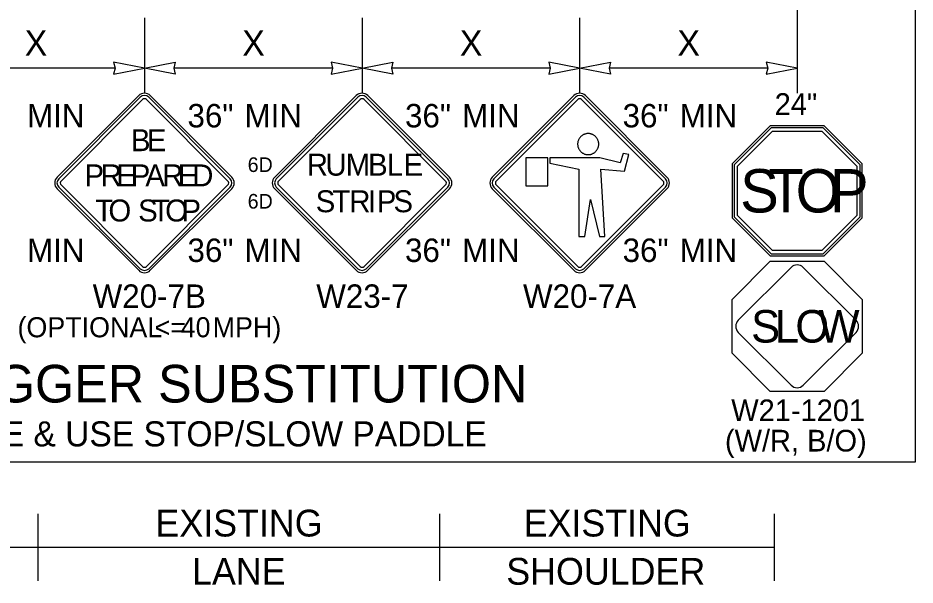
# Model space of a CAD drawing. Extents: x 99999.1 to 100095.7, y 99995 to 100010.7.
# Drawn here: x 100006.43 to 100009.11, y 100003.112 to 100004.807 of the extents above; entities that cross this region are included whole.
import ezdxf

# ---------------------------------------------------------------- set-up
doc = ezdxf.new("R2010")
doc.units = 0
for name, color, linetype in [('SH_DE_DetailHeading2Text', 7, 'Continuous'), ('TR_SN_ConstructionSigns', 7, 'Continuous'), ('TR_WZ_WorkZoneDetails', 7, 'Continuous'), ('TR_WZ_WorkZoneTextCurrent', 7, 'Continuous')]:
    doc.layers.add(name, color=color, linetype=linetype)

msp = doc.modelspace()

# ---------------------------------------------------------------- linework, layer by layer
at = {"layer": 'TR_SN_ConstructionSigns'}
for p, q in [((100006.7907, 100004.5751), (100006.5471, 100004.3315)), ((100007.0691, 100004.3315), (100006.8255, 100004.5751)), ((100007.4407, 100004.5751), (100007.1971, 100004.3315)), ((100007.7191, 100004.3315), (100007.4755, 100004.5751)), ((100008.0907, 100004.5751), (100007.8471, 100004.3315)), ((100008.3691, 100004.3315), (100008.1255, 100004.5751)), ((100006.7955, 100004.5703), (100006.5519, 100004.3267)), ((100006.5587, 100004.3199), (100006.8023, 100004.5635)), ((100006.8139, 100004.5635), (100007.0575, 100004.3199)), ((100007.0643, 100004.3267), (100006.8207, 100004.5703)), ((100007.4455, 100004.5703), (100007.2019, 100004.3267)), ((100007.2087, 100004.3199), (100007.4523, 100004.5635)), ((100007.4639, 100004.5635), (100007.7075, 100004.3199)), ((100007.7143, 100004.3267), (100007.4707, 100004.5703)), ((100008.0955, 100004.5703), (100007.8519, 100004.3267)), ((100007.8587, 100004.3199), (100008.1023, 100004.5635)), ((100008.1139, 100004.5635), (100008.3575, 100004.3199)), ((100008.3643, 100004.3267), (100008.1207, 100004.5703)), ((100008.6775, 100004.4851), (100008.5636, 100004.3713)), ((100008.68, 100004.4791), (100008.5697, 100004.3687)), ((100008.5798, 100004.3646), (100008.6842, 100004.4689)), ((100008.8385, 100004.4851), (100008.6775, 100004.4851)), ((100008.836, 100004.4791), (100008.68, 100004.4791)), ((100008.6842, 100004.4689), (100008.8318, 100004.4689)), ((100008.8318, 100004.4689), (100008.9362, 100004.3646)), ((100008.9463, 100004.3687), (100008.836, 100004.4791)), ((100008.9524, 100004.3713), (100008.8385, 100004.4851)), ((100008.1043, 100004.4417), (100008.1037, 100004.4401)), ((100008.1049, 100004.4433), (100008.1043, 100004.4417)), ((100008.1056, 100004.4448), (100008.1049, 100004.4433)), ((100008.1064, 100004.4463), (100008.1056, 100004.4448)), ((100008.1074, 100004.4477), (100008.1064, 100004.4463)), ((100008.1083, 100004.4491), (100008.1074, 100004.4477)), ((100008.1093, 100004.4504), (100008.1083, 100004.4491)), ((100008.1104, 100004.4516), (100008.1093, 100004.4504)), ((100008.1116, 100004.4528), (100008.1104, 100004.4516)), ((100008.1128, 100004.454), (100008.1116, 100004.4528)), ((100008.1142, 100004.455), (100008.1128, 100004.454)), ((100008.1155, 100004.456), (100008.1142, 100004.455)), ((100008.1169, 100004.4569), (100008.1155, 100004.456)), ((100008.1183, 100004.4578), (100008.1169, 100004.4569)), ((100008.1199, 100004.4586), (100008.1183, 100004.4578)), ((100008.1213, 100004.4593), (100008.1199, 100004.4586)), ((100008.1229, 100004.4599), (100008.1213, 100004.4593)), ((100008.1245, 100004.4604), (100008.1229, 100004.4599)), ((100008.1262, 100004.4608), (100008.1245, 100004.4604)), ((100008.1278, 100004.4612), (100008.1262, 100004.4608)), ((100008.1294, 100004.4615), (100008.1278, 100004.4612)), ((100008.1311, 100004.4616), (100008.1294, 100004.4615)), ((100008.1328, 100004.4618), (100008.1311, 100004.4616)), ((100008.1345, 100004.4618), (100008.1328, 100004.4618)), ((100008.1361, 100004.4616), (100008.1345, 100004.4618)), ((100008.1378, 100004.4615), (100008.1361, 100004.4616)), ((100008.1395, 100004.4612), (100008.1378, 100004.4615)), ((100008.1411, 100004.4608), (100008.1395, 100004.4612)), ((100008.1427, 100004.4604), (100008.1411, 100004.4608)), ((100008.1443, 100004.4599), (100008.1427, 100004.4604)), ((100008.1459, 100004.4593), (100008.1443, 100004.4599)), ((100008.1474, 100004.4586), (100008.1459, 100004.4593)), ((100008.1489, 100004.4578), (100008.1474, 100004.4586)), ((100008.1503, 100004.4569), (100008.1489, 100004.4578)), ((100008.1517, 100004.456), (100008.1503, 100004.4569)), ((100008.1531, 100004.455), (100008.1517, 100004.456)), ((100008.1543, 100004.454), (100008.1531, 100004.455)), ((100008.1556, 100004.4528), (100008.1543, 100004.454)), ((100008.1568, 100004.4516), (100008.1556, 100004.4528)), ((100008.1579, 100004.4504), (100008.1568, 100004.4516)), ((100008.1589, 100004.4491), (100008.1579, 100004.4504)), ((100008.1599, 100004.4477), (100008.1589, 100004.4491)), ((100008.1608, 100004.4463), (100008.1599, 100004.4477)), ((100008.1616, 100004.4448), (100008.1608, 100004.4463)), ((100008.1623, 100004.4433), (100008.1616, 100004.4448)), ((100008.1629, 100004.4417), (100008.1623, 100004.4433)), ((100008.1635, 100004.4401), (100008.1629, 100004.4417)), ((100008.1023, 100004.4336), (100008.1021, 100004.4319)), ((100008.1021, 100004.4319), (100008.1021, 100004.4302)), ((100008.1021, 100004.4302), (100008.1021, 100004.4286)), ((100008.1021, 100004.4286), (100008.1023, 100004.4269)), ((100008.1025, 100004.4353), (100008.1023, 100004.4336)), ((100008.1023, 100004.4269), (100008.1025, 100004.4252)), ((100008.1028, 100004.4369), (100008.1025, 100004.4353)), ((100008.1025, 100004.4252), (100008.1028, 100004.4236)), ((100008.1032, 100004.4385), (100008.1028, 100004.4369)), ((100008.1028, 100004.4236), (100008.1032, 100004.422)), ((100008.1037, 100004.4401), (100008.1032, 100004.4385)), ((100008.1032, 100004.422), (100008.1037, 100004.4204)), ((100008.1037, 100004.4204), (100008.1043, 100004.4188)), ((100008.1043, 100004.4188), (100008.1049, 100004.4172)), ((100008.1049, 100004.4172), (100008.1056, 100004.4157)), ((100008.1056, 100004.4157), (100008.1064, 100004.4142)), ((100008.1064, 100004.4142), (100008.1074, 100004.4128)), ((100008.1599, 100004.4128), (100008.1608, 100004.4142)), ((100008.1608, 100004.4142), (100008.1616, 100004.4157)), ((100008.1616, 100004.4157), (100008.1623, 100004.4172)), ((100008.1623, 100004.4172), (100008.1629, 100004.4188)), ((100008.1629, 100004.4188), (100008.1635, 100004.4204)), ((100008.164, 100004.4385), (100008.1635, 100004.4401)), ((100008.1635, 100004.4204), (100008.164, 100004.422)), ((100008.1644, 100004.4369), (100008.164, 100004.4385)), ((100008.164, 100004.422), (100008.1644, 100004.4236)), ((100008.1647, 100004.4353), (100008.1644, 100004.4369)), ((100008.1644, 100004.4236), (100008.1647, 100004.4252)), ((100008.165, 100004.4336), (100008.1647, 100004.4353)), ((100008.1647, 100004.4252), (100008.165, 100004.4269)), ((100008.1651, 100004.4319), (100008.165, 100004.4336)), ((100008.165, 100004.4269), (100008.1651, 100004.4286)), ((100008.1651, 100004.4302), (100008.1651, 100004.4319)), ((100008.1651, 100004.4286), (100008.1651, 100004.4302)), ((100007.9469, 100004.3888), (100007.9469, 100004.306)), ((100008.0128, 100004.3888), (100007.9469, 100004.3888)), ((100008.0128, 100004.306), (100008.0128, 100004.3888)), ((100008.1689, 100004.3888), (100008.0189, 100004.3888)), ((100008.0189, 100004.3888), (100008.0189, 100004.373)), ((100008.1074, 100004.4128), (100008.1083, 100004.4114)), ((100008.1083, 100004.4114), (100008.1093, 100004.4101)), ((100008.1093, 100004.4101), (100008.1104, 100004.4089)), ((100008.1104, 100004.4089), (100008.1116, 100004.4077)), ((100008.1116, 100004.4077), (100008.1128, 100004.4065)), ((100008.1128, 100004.4065), (100008.1142, 100004.4055)), ((100008.1142, 100004.4055), (100008.1155, 100004.4044)), ((100008.1155, 100004.4044), (100008.1169, 100004.4035)), ((100008.1169, 100004.4035), (100008.1183, 100004.4027)), ((100008.1183, 100004.4027), (100008.1199, 100004.4019)), ((100008.1199, 100004.4019), (100008.1213, 100004.4012)), ((100008.1213, 100004.4012), (100008.1229, 100004.4006)), ((100008.1229, 100004.4006), (100008.1245, 100004.4001)), ((100008.1245, 100004.4001), (100008.1262, 100004.3996)), ((100008.1262, 100004.3996), (100008.1278, 100004.3993)), ((100008.1278, 100004.3993), (100008.1294, 100004.399)), ((100008.1294, 100004.399), (100008.1311, 100004.3988)), ((100008.1311, 100004.3988), (100008.1328, 100004.3987)), ((100008.1328, 100004.3987), (100008.1345, 100004.3987)), ((100008.1345, 100004.3987), (100008.1361, 100004.3988)), ((100008.1361, 100004.3988), (100008.1378, 100004.399)), ((100008.1378, 100004.399), (100008.1395, 100004.3993)), ((100008.1395, 100004.3993), (100008.1411, 100004.3996)), ((100008.1411, 100004.3996), (100008.1427, 100004.4001)), ((100008.1427, 100004.4001), (100008.1443, 100004.4006)), ((100008.1443, 100004.4006), (100008.1459, 100004.4012)), ((100008.1459, 100004.4012), (100008.1474, 100004.4019)), ((100008.1474, 100004.4019), (100008.1489, 100004.4027)), ((100008.1489, 100004.4027), (100008.1503, 100004.4035)), ((100008.1503, 100004.4035), (100008.1517, 100004.4044)), ((100008.1517, 100004.4044), (100008.1531, 100004.4055)), ((100008.1531, 100004.4055), (100008.1543, 100004.4065)), ((100008.1543, 100004.4065), (100008.1556, 100004.4077)), ((100008.1556, 100004.4077), (100008.1568, 100004.4089)), ((100008.1568, 100004.4089), (100008.1579, 100004.4101)), ((100008.1579, 100004.4101), (100008.1589, 100004.4114)), ((100008.1589, 100004.4114), (100008.1599, 100004.4128)), ((100008.2297, 100004.3738), (100008.1689, 100004.3888)), ((100008.2382, 100004.4026), (100008.2297, 100004.3738)), ((100008.2556, 100004.3995), (100008.2382, 100004.4026)), ((100008.2425, 100004.3497), (100008.2556, 100004.3995)), ((100008.0189, 100004.373), (100008.106, 100004.3557)), ((100008.5636, 100004.3713), (100008.5636, 100004.2102)), ((100008.5697, 100004.3687), (100008.5697, 100004.2127)), ((100008.5798, 100004.2169), (100008.5798, 100004.3646)), ((100008.9362, 100004.3646), (100008.9362, 100004.2169)), ((100008.9463, 100004.2127), (100008.9463, 100004.3687)), ((100008.9524, 100004.2102), (100008.9524, 100004.3713)), ((100008.106, 100004.3557), (100008.106, 100004.1541)), ((100008.1831, 100004.1541), (100008.1717, 100004.3558)), ((100008.1717, 100004.3558), (100008.2425, 100004.3497)), ((100006.8023, 100004.0647), (100006.5587, 100004.3083)), ((100007.0575, 100004.3083), (100006.8139, 100004.0647)), ((100007.4523, 100004.0647), (100007.2087, 100004.3083)), ((100007.7075, 100004.3083), (100007.4639, 100004.0647)), ((100008.1023, 100004.0647), (100007.8587, 100004.3083)), ((100008.3575, 100004.3083), (100008.1139, 100004.0647)), ((100006.5471, 100004.2967), (100006.7907, 100004.0531)), ((100006.5519, 100004.3015), (100006.7955, 100004.0579)), ((100006.8207, 100004.0579), (100007.0643, 100004.3015)), ((100006.8255, 100004.0531), (100007.0691, 100004.2967)), ((100007.1971, 100004.2967), (100007.4407, 100004.0531)), ((100007.2019, 100004.3015), (100007.4455, 100004.0579)), ((100007.4707, 100004.0579), (100007.7143, 100004.3015)), ((100007.4755, 100004.0531), (100007.7191, 100004.2967)), ((100007.8471, 100004.2967), (100008.0907, 100004.0531)), ((100007.8519, 100004.3015), (100008.0955, 100004.0579)), ((100007.9469, 100004.306), (100008.0128, 100004.306)), ((100008.1207, 100004.0579), (100008.3643, 100004.3015)), ((100008.1255, 100004.0531), (100008.3691, 100004.2967)), ((100008.1236, 100004.1541), (100008.1408, 100004.265)), ((100008.1408, 100004.265), (100008.1673, 100004.1541)), ((100008.5636, 100004.2102), (100008.6775, 100004.0963)), ((100008.5697, 100004.2127), (100008.68, 100004.1024)), ((100008.6842, 100004.1125), (100008.5798, 100004.2169)), ((100008.9362, 100004.2169), (100008.8318, 100004.1125)), ((100008.836, 100004.1024), (100008.9463, 100004.2127)), ((100008.8385, 100004.0963), (100008.9524, 100004.2102)), ((100008.106, 100004.1541), (100008.1236, 100004.1541)), ((100008.1673, 100004.1541), (100008.1831, 100004.1541)), ((100008.6775, 100004.0963), (100008.8385, 100004.0963)), ((100008.68, 100004.1024), (100008.836, 100004.1024)), ((100008.8318, 100004.1125), (100008.6842, 100004.1125)), ((100008.7397, 100004.0618), (100008.5819, 100003.9041)), ((100008.9341, 100003.9041), (100008.7763, 100004.0618)), ((100008.5819, 100003.8674), (100008.7397, 100003.7097)), ((100008.7763, 100003.7097), (100008.9341, 100003.8674))]:
    msp.add_line(p, q, dxfattribs=at)
msp.add_lwpolyline([(100008.9524, 100003.9663), (100008.9524, 100003.8052), (100008.8385, 100003.6913), (100008.6775, 100003.6913), (100008.5636, 100003.8052), (100008.5636, 100003.9663), (100008.6775, 100004.0801), (100008.8385, 100004.0801)], close=True, dxfattribs=at)
for centre, radius, start, end in [((100006.8081, 100004.5577), 0.0246, 45, 135), ((100006.8081, 100004.5577), 0.0178, 45, 135), ((100007.4581, 100004.5577), 0.0246, 45, 135), ((100007.4581, 100004.5577), 0.0178, 45, 135), ((100008.1081, 100004.5577), 0.0246, 45, 135), ((100008.1081, 100004.5577), 0.0178, 45, 135), ((100006.8081, 100004.5577), 0.0082, 45, 135), ((100007.4581, 100004.5577), 0.0082, 45, 135), ((100008.1081, 100004.5577), 0.0082, 45, 135), ((100006.5645, 100004.3141), 0.0246, 135, 225), ((100006.5645, 100004.3141), 0.0178, 135, 225), ((100006.5645, 100004.3141), 0.0082, 135, 225), ((100007.0517, 100004.3141), 0.0082, 315, 45), ((100007.0517, 100004.3141), 0.0178, 315, 45), ((100007.0517, 100004.3141), 0.0246, 315, 45), ((100007.2145, 100004.3141), 0.0246, 135, 225), ((100007.2145, 100004.3141), 0.0178, 135, 225), ((100007.2145, 100004.3141), 0.0082, 135, 225), ((100007.7017, 100004.3141), 0.0082, 315, 45), ((100007.7017, 100004.3141), 0.0178, 315, 45), ((100007.7017, 100004.3141), 0.0246, 315, 45), ((100007.8645, 100004.3141), 0.0246, 135, 225), ((100007.8645, 100004.3141), 0.0178, 135, 225), ((100007.8645, 100004.3141), 0.0082, 135, 225), ((100008.3517, 100004.3141), 0.0082, 315, 45), ((100008.3517, 100004.3141), 0.0178, 315, 45), ((100008.3517, 100004.3141), 0.0246, 315, 45), ((100008.758, 100004.0435), 0.0259, 45, 135), ((100006.8081, 100004.0705), 0.0246, 225, 315), ((100006.8081, 100004.0705), 0.0178, 225, 315), ((100006.8081, 100004.0705), 0.0082, 225, 315), ((100007.4581, 100004.0705), 0.0246, 225, 315), ((100007.4581, 100004.0705), 0.0178, 225, 315), ((100007.4581, 100004.0705), 0.0082, 225, 315), ((100008.1081, 100004.0705), 0.0246, 225, 315), ((100008.1081, 100004.0705), 0.0178, 225, 315), ((100008.1081, 100004.0705), 0.0082, 225, 315), ((100008.6003, 100003.8857), 0.0259, 135, 225), ((100008.9157, 100003.8857), 0.0259, 315, 45), ((100008.758, 100003.728), 0.0259, 225, 315)]:
    msp.add_arc(centre, radius, start, end, dxfattribs=at)
at = {"layer": 'TR_WZ_WorkZoneDetails'}
for p, q in [((100008.7581, 100005.0573), (100008.7581, 100004.5823)), ((100006.8081, 100004.8073), (100006.8081, 100004.5823)), ((100007.4581, 100004.8073), (100007.4581, 100004.5823)), ((100008.1081, 100004.8073), (100008.1081, 100004.5823)), ((100006.7202, 100004.6573), (100006.246, 100004.6573)), ((100007.3702, 100004.6573), (100006.896, 100004.6573)), ((100008.0202, 100004.6573), (100007.546, 100004.6573)), ((100008.6702, 100004.6573), (100008.196, 100004.6573)), ((100006.4907, 100003.1255), (100006.4907, 100003.3255)), ((100007.6907, 100003.1255), (100007.6907, 100003.3255)), ((100008.6907, 100003.1255), (100008.6907, 100003.3255)), ((100005.2907, 100003.2255), (100006.4907, 100003.2255)), ((100006.4907, 100003.2255), (100007.6907, 100003.2255)), ((100007.6907, 100003.2255), (100008.6907, 100003.2255))]:
    msp.add_line(p, q, dxfattribs=at)
for points in [[(100006.8081, 100004.6573), (100006.7159, 100004.6754), (100006.7202, 100004.6573), (100006.7159, 100004.6393)], [(100006.8081, 100004.6573), (100006.9002, 100004.6754), (100006.896, 100004.6573), (100006.9002, 100004.6393)], [(100007.4581, 100004.6573), (100007.3659, 100004.6754), (100007.3702, 100004.6573), (100007.3659, 100004.6393)], [(100007.4581, 100004.6573), (100007.5502, 100004.6754), (100007.546, 100004.6573), (100007.5502, 100004.6393)], [(100008.1081, 100004.6573), (100008.0159, 100004.6754), (100008.0202, 100004.6573), (100008.0159, 100004.6393)], [(100008.1081, 100004.6573), (100008.2002, 100004.6754), (100008.196, 100004.6573), (100008.2002, 100004.6393)], [(100008.7581, 100004.6573), (100008.6659, 100004.6754), (100008.6702, 100004.6573), (100008.6659, 100004.6393)]]:
    msp.add_lwpolyline(points, close=True, dxfattribs=at)
at = {"layer": 'TR_WZ_WorkZoneTextCurrent'}
msp.add_lwpolyline([(100005.1015, 100005.5823), (100009.1102, 100005.5823), (100009.1102, 100003.4799), (100005.1015, 100003.4799)], close=True, dxfattribs=at)

# ---------------------------------------------------------------- texts
at = {"layer": 'SH_DE_DetailHeading2Text'}
msp.add_text('HUMAN FLAGGER SUBSTITUTION', height=0.1125, rotation=360, dxfattribs=at).set_placement((100005.4946, 100003.658))
at = {"layer": 'TR_SN_ConstructionSigns'}
for s, height, p in [('24"', 0.0648, (100008.6908, 100004.5175)), ('B', 0.0656, (100006.7676, 100004.4091)), ('E', 0.0656, (100006.8151, 100004.4091)), ('6D', 0.04375, (100007.1164, 100004.3469)), ('R', 0.0656, (100007.293, 100004.336)), ('U', 0.0656, (100007.3488, 100004.336)), ('M', 0.0656, (100007.4092, 100004.336)), ('B', 0.0656, (100007.4761, 100004.336)), ('L', 0.0656, (100007.5319, 100004.336)), ('E', 0.0656, (100007.5824, 100004.336)), ('P', 0.0656, (100006.6288, 100004.304)), ('R', 0.0656, (100006.6771, 100004.304)), ('E', 0.0656, (100006.7237, 100004.304)), ('P', 0.0656, (100006.767, 100004.304)), ('A', 0.0656, (100006.8107, 100004.304)), ('R', 0.0656, (100006.8608, 100004.304)), ('E', 0.0656, (100006.9073, 100004.304)), ('D', 0.0656, (100006.9506, 100004.304)), ('S', 0.1296, (100008.5876, 100004.2259)), ('T', 0.1296, (100008.6718, 100004.2259)), ('O', 0.1296, (100008.7535, 100004.2259)), ('P', 0.1296, (100008.8559, 100004.2259)), ('6D', 0.04375, (100007.1164, 100004.2375)), ('S', 0.0656, (100007.3196, 100004.2266)), ('T', 0.0656, (100007.3695, 100004.2266)), ('R', 0.0656, (100007.42, 100004.2266)), ('I', 0.0656, (100007.4758, 100004.2266)), ('P', 0.0656, (100007.5021, 100004.2266)), ('S', 0.0656, (100007.5519, 100004.2266)), ('T', 0.0656, (100006.6609, 100004.199)), ('O', 0.0656, (100006.7003, 100004.199)), ('S', 0.0656, (100006.7891, 100004.199)), ('T', 0.0656, (100006.8303, 100004.199)), ('O', 0.0656, (100006.8698, 100004.199)), ('P', 0.0656, (100006.9185, 100004.199)), ('S', 0.0972, (100008.6205, 100003.8371)), ('L', 0.0972, (100008.6914, 100003.8371)), ('O', 0.0972, (100008.7527, 100003.8371)), ('W', 0.0972, (100008.8217, 100003.8371))]:
    msp.add_text(s, height=height, dxfattribs=at).set_placement(p)
for s, height, p in [('MIN', 0.07, (100006.4571, 100004.4802)), ('36"', 0.07, (100006.9365, 100004.4802)), ('MIN', 0.07, (100007.1071, 100004.4802)), ('36"', 0.07, (100007.5865, 100004.4802)), ('MIN', 0.07, (100007.7571, 100004.4802)), ('36"', 0.07, (100008.2365, 100004.4802)), ('MIN', 0.07, (100008.4071, 100004.4802)), ('MIN', 0.07, (100006.4571, 100004.078)), ('36"', 0.07, (100006.9365, 100004.078)), ('MIN', 0.07, (100007.1071, 100004.078)), ('36"', 0.07, (100007.5865, 100004.078)), ('MIN', 0.07, (100007.7571, 100004.078)), ('36"', 0.07, (100008.2365, 100004.078)), ('MIN', 0.07, (100008.4071, 100004.078)), ('W20-7B', 0.07, (100006.6533, 100003.9409)), ('W23-7', 0.07, (100007.3214, 100003.9409)), ('W20-7A', 0.07, (100007.939, 100003.9409)), ('(OPTIONAL', 0.06, (100006.4287, 100003.8529)), ('40', 0.06, (100006.9162, 100003.8529)), ('MPH)', 0.06, (100007.0117, 100003.8529)), ('<=', 0.06, (100006.8384, 100003.8529)), ('W21-1201', 0.0648, (100008.5611, 100003.6022)), ('(W/R, B/O)', 0.0648, (100008.5423, 100003.5115))]:
    msp.add_text(s, height=height, rotation=360, dxfattribs=at).set_placement(p)
at = {"layer": 'TR_WZ_WorkZoneDetails'}
for s, p in [('EXISTING', (100006.8409, 100003.2575)), ('EXISTING', (100007.9409, 100003.2575)), ('LANE', (100006.9503, 100003.1135)), ('SHOULDER', (100007.889, 100003.1135))]:
    msp.add_text(s, height=0.08, rotation=360, dxfattribs=at).set_placement(p)
at = {"layer": 'TR_WZ_WorkZoneTextCurrent'}
for p in [(100006.4505, 100004.6948), (100007.1005, 100004.6948), (100007.7505, 100004.6948), (100008.4005, 100004.6948)]:
    msp.add_text('X', height=0.075, rotation=360, dxfattribs=at).set_placement(p)
msp.add_text('UPDATE SIGNAGE & USE STOP/SLOW PADDLE', height=0.075, dxfattribs=at).set_placement((100005.5568, 100003.5268))

doc.saveas('drawing.dxf')
